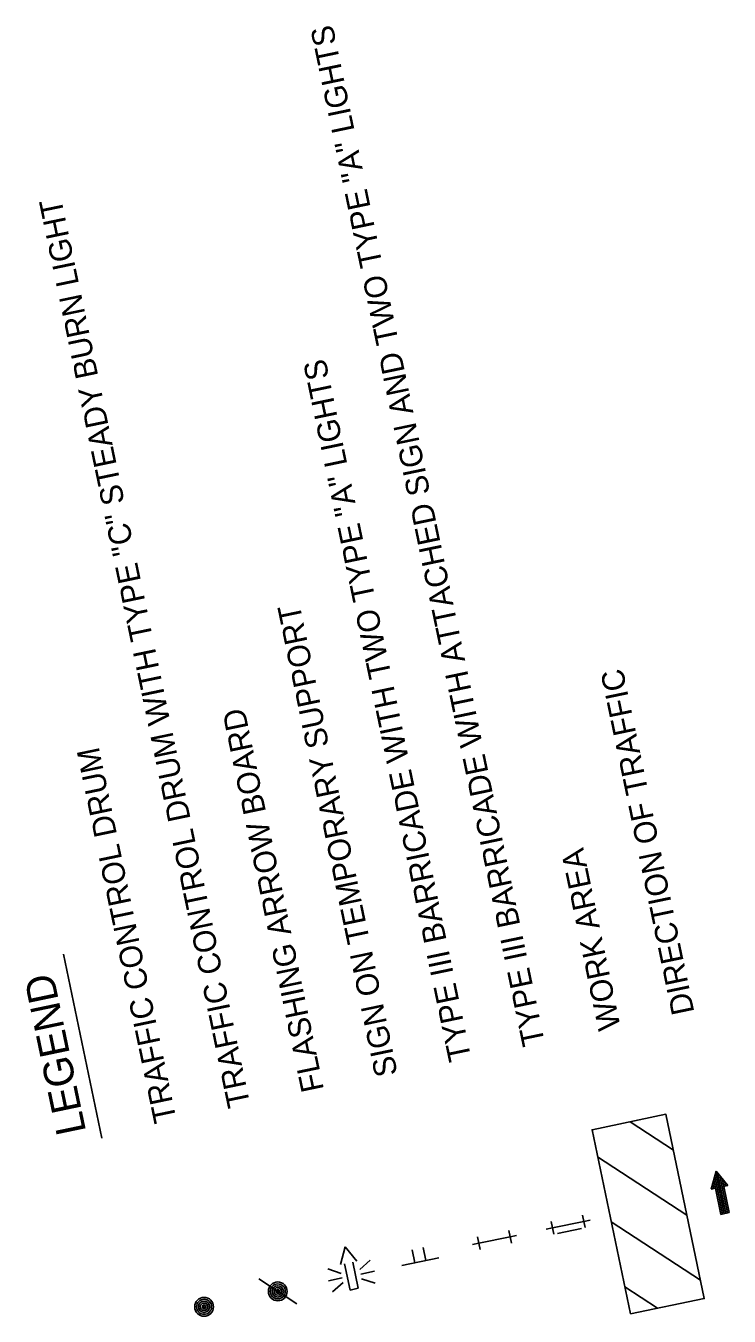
# Model space of a CAD drawing. Extents: x 361679 to 361866, y 127143 to 127486.
import ezdxf

# ---------------------------------------------------------------- set-up
doc = ezdxf.new("R2010")
doc.units = 0
for name, color, linetype in [('P_TC', 7, 'Continuous'), ('P_TC_FlowArrow', 7, 'Continuous'), ('P_TC_Text', 7, 'Continuous')]:
    doc.layers.add(name, color=color, linetype=linetype)

msp = doc.modelspace()

# ---------------------------------------------------------------- linework, layer by layer
at = {"layer": 'P_TC'}
for p, q in [((361851.44, 127187.04), (361839.97, 127194.55)), ((361855.05, 127169.73), (361831.32, 127185.27)), ((361827.3, 127169.75), (361827.65, 127168.09)), ((361807.72, 127165.66), (361808.06, 127164)), ((361819.32, 127166.37), (361817.66, 127166.02)), ((361819.32, 127166.37), (361818.98, 127168.03)), ((361827.65, 127168.09), (361819.32, 127166.37)), ((361819.32, 127166.37), (361819.67, 127164.7)), ((361827.01, 127166.22), (361820.65, 127164.9)), ((361827.65, 127168.09), (361829.31, 127168.43)), ((361827.65, 127168.09), (361827.99, 127166.42)), ((361858.66, 127152.43), (361834.93, 127167.96)), ((361799.74, 127162.28), (361798.08, 127161.93)), ((361799.74, 127162.28), (361799.4, 127163.94)), ((361808.06, 127164), (361799.74, 127162.28)), ((361799.74, 127162.28), (361800.08, 127160.61)), ((361808.06, 127164), (361809.73, 127164.34)), ((361808.06, 127164), (361808.41, 127162.33)), ((361762.96, 127156.59), (361764.24, 127161.34)), ((361764.24, 127161.34), (361767.37, 127157.51)), ((361782.74, 127157.11), (361782.02, 127160.54)), ((361785.67, 127157.72), (361784.96, 127161.15)), ((361763.18, 127154.27), (361759.61, 127155.44)), ((361765.52, 127149.84), (361764.07, 127156.81)), ((361766.27, 127157.28), (361767.72, 127150.3)), ((361768.1, 127155.3), (361770.9, 127157.8)), ((361789.1, 127158.44), (361779.31, 127156.4)), ((361751.36, 127146.17), (361741.27, 127152.78)), ((361763.43, 127153.05), (361759.76, 127152.28)), ((361763.69, 127151.82), (361760.89, 127149.32)), ((361768.36, 127154.07), (361772.03, 127154.84)), ((361768.61, 127152.85), (361772.18, 127151.68)), ((361767.72, 127150.3), (361765.52, 127149.84)), ((361847.21, 127144.99), (361838.54, 127150.66))]:
    msp.add_line(p, q, dxfattribs=at)
msp.add_lwpolyline([(361840.04, 127143.49), (361829.83, 127192.44), (361849.46, 127196.53), (361859.67, 127147.59)], close=True, dxfattribs=at)
for centre, radius in [((361746.32, 127149.48), 2.5), ((361746.32, 127149.48), 2), ((361746.32, 127149.48), 1.5), ((361746.32, 127149.48), 1), ((361746.32, 127149.48), 0.5), ((361746.32, 127149.48), 0.25), ((361726.74, 127145.39), 2.5), ((361726.74, 127145.39), 2), ((361726.74, 127145.39), 1.5), ((361726.74, 127145.39), 1), ((361726.74, 127145.39), 0.5), ((361726.74, 127145.39), 0.25)]:
    msp.add_circle(centre, radius, dxfattribs=at)
at = {"layer": 'P_TC_FlowArrow'}
for p, q in [((361862.8, 127181.44), (361861.52, 127176.68)), ((361862.62, 127176.94), (361862.17, 127179.1)), ((361864.52, 127170.03), (361862.43, 127180.06)), ((361864.96, 127170.12), (361862.69, 127181.03)), ((361862.8, 127181.44), (361865.93, 127177.6)), ((361865.4, 127170.21), (361863.15, 127181)), ((361865.84, 127170.31), (361863.77, 127180.25)), ((361864.82, 127177.4), (361864.39, 127179.49)), ((361861.52, 127176.68), (361865.93, 127177.6)), ((361861.74, 127176.75), (361861.65, 127177.17)), ((361862.18, 127176.84), (361861.91, 127178.13)), ((361864.08, 127169.94), (361862.63, 127176.91)), ((361866.28, 127170.4), (361864.83, 127177.37)), ((361865.26, 127177.49), (361865, 127178.74)), ((361865.7, 127177.58), (361865.62, 127177.98)), ((361864.08, 127169.94), (361866.28, 127170.4)), ((361865.18, 127170.17), (361865.18, 127170.17))]:
    msp.add_line(p, q, dxfattribs=at)
at = {"layer": 'P_TC_Text'}
msp.add_line((361699.6, 127190.2), (361689.41, 127239.06), dxfattribs=at)

# ---------------------------------------------------------------- texts
for s, height, p in [('TYPE III BARRICADE WITH ATTACHED SIGN AND TWO TYPE "A" LIGHTS', 6, (361817.36, 127215.37)), ('TRAFFIC CONTROL DRUM WITH TYPE "C" STEADY BURN LIGHT', 6, (361739.04, 127199.03)), ('TYPE III BARRICADE WITH TWO TYPE "A" LIGHTS', 6, (361797.78, 127211.29)), ('SIGN ON TEMPORARY SUPPORT', 6, (361778.2, 127207.2)), ('DIRECTION OF TRAFFIC', 6, (361857.05, 127223.65)), ('FLASHING ARROW BOARD', 6, (361758.62, 127203.12)), ('TRAFFIC CONTROL DRUM', 6, (361719.46, 127194.95)), ('WORK AREA', 6, (361837.48, 127219.57)), ('LEGEND', 7.88, (361695.42, 127191.97))]:
    msp.add_text(s, height=height, rotation=101.7841, dxfattribs=at).set_placement(p)

doc.saveas('drawing.dxf')
